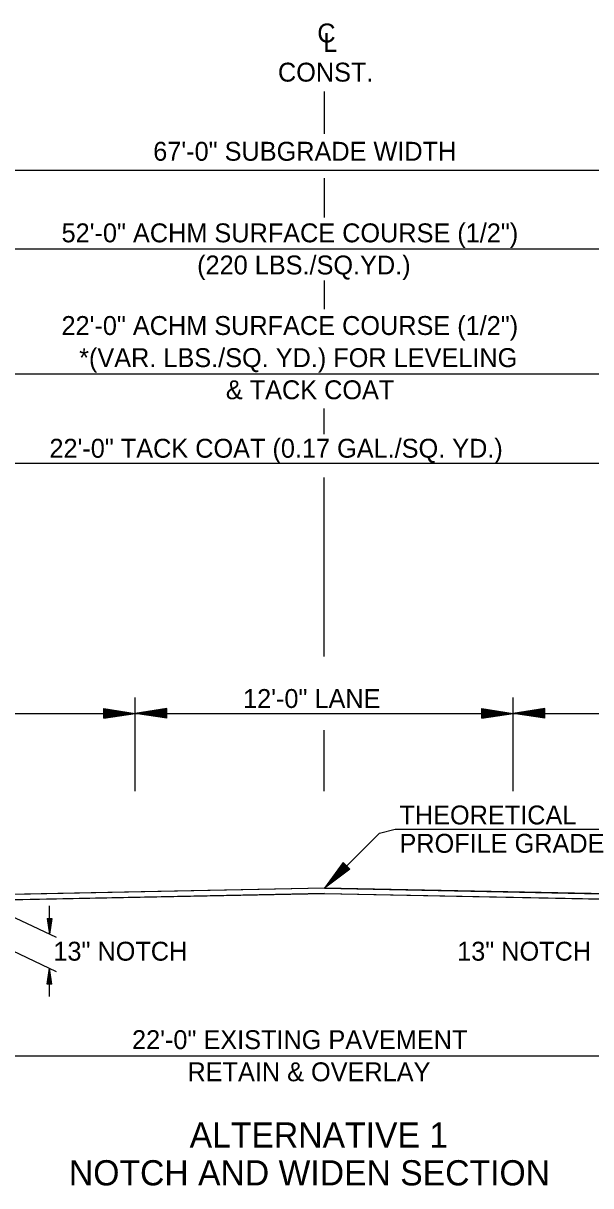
# Model space of a CAD drawing. Extents: x 1371763 to 1372860, y 385599 to 385872.
# Drawn here: x 1372073.83 to 1372091.85, y 385769.36 to 385806.27 of the extents above; entities that cross this region are included whole.
import ezdxf

# ---------------------------------------------------------------- set-up
doc = ezdxf.new("R2010")
doc.units = 0
doc.layers.add('R_Draft', color=7, linetype='Continuous')

msp = doc.modelspace()

# ---------------------------------------------------------------- linework, layer by layer
at = {"layer": 'R_Draft'}
for p, q in [((1372083.395, 385802.752), (1372083.395, 385804.102)), ((1372049.964, 385801.602), (1372116.827, 385801.602)), ((1372083.395, 385800.102), (1372083.395, 385801.352)), ((1372057.395, 385799.102), (1372109.395, 385799.102)), ((1372083.395, 385797.193), (1372083.395, 385798.102)), ((1372072.395, 385795.139), (1372094.395, 385795.14)), ((1372083.392, 385793.221), (1372083.392, 385794.031)), ((1372072.395, 385792.301), (1372094.395, 385792.301)), ((1372083.394, 385786.16), (1372083.392, 385791.841)), ((1372077.392, 385781.89), (1372077.393, 385784.864)), ((1372089.392, 385781.89), (1372089.393, 385784.864)), ((1372065.393, 385784.357), (1372077.393, 385784.357)), ((1372076.393, 385784.507), (1372077.393, 385784.357)), ((1372076.393, 385784.207), (1372076.393, 385784.507)), ((1372076.393, 385784.482), (1372077.226, 385784.357)), ((1372076.393, 385784.456), (1372077.054, 385784.357)), ((1372076.393, 385784.431), (1372076.887, 385784.357)), ((1372076.393, 385784.406), (1372076.718, 385784.357)), ((1372076.393, 385784.38), (1372076.551, 385784.357)), ((1372076.393, 385784.207), (1372077.393, 385784.357)), ((1372076.393, 385784.308), (1372076.718, 385784.357)), ((1372076.393, 385784.257), (1372077.054, 385784.357)), ((1372076.393, 385784.232), (1372077.226, 385784.357)), ((1372076.393, 385784.282), (1372076.887, 385784.357)), ((1372076.393, 385784.333), (1372076.551, 385784.357)), ((1372078.393, 385784.507), (1372077.393, 385784.357)), ((1372078.393, 385784.207), (1372077.393, 385784.357)), ((1372077.393, 385784.357), (1372089.393, 385784.357)), ((1372078.393, 385784.482), (1372077.56, 385784.357)), ((1372078.393, 385784.232), (1372077.56, 385784.357)), ((1372078.393, 385784.456), (1372077.732, 385784.357)), ((1372078.393, 385784.257), (1372077.732, 385784.357)), ((1372078.393, 385784.431), (1372077.898, 385784.357)), ((1372078.393, 385784.282), (1372077.898, 385784.357)), ((1372078.393, 385784.406), (1372078.068, 385784.357)), ((1372078.393, 385784.308), (1372078.068, 385784.357)), ((1372078.393, 385784.38), (1372078.235, 385784.357)), ((1372078.393, 385784.333), (1372078.235, 385784.357)), ((1372078.393, 385784.207), (1372078.393, 385784.507)), ((1372088.393, 385784.507), (1372089.393, 385784.357)), ((1372088.393, 385784.207), (1372088.393, 385784.507)), ((1372088.393, 385784.482), (1372089.226, 385784.357)), ((1372088.393, 385784.456), (1372089.054, 385784.357)), ((1372088.393, 385784.431), (1372088.887, 385784.357)), ((1372088.393, 385784.406), (1372088.718, 385784.357)), ((1372088.393, 385784.38), (1372088.551, 385784.357)), ((1372088.393, 385784.207), (1372089.393, 385784.357)), ((1372088.393, 385784.308), (1372088.718, 385784.357)), ((1372088.393, 385784.257), (1372089.054, 385784.357)), ((1372088.393, 385784.232), (1372089.226, 385784.357)), ((1372088.393, 385784.282), (1372088.887, 385784.357)), ((1372088.393, 385784.333), (1372088.551, 385784.357)), ((1372090.393, 385784.507), (1372089.393, 385784.357)), ((1372089.393, 385784.357), (1372101.393, 385784.357)), ((1372090.393, 385784.207), (1372089.393, 385784.357)), ((1372090.393, 385784.482), (1372089.56, 385784.357)), ((1372090.393, 385784.232), (1372089.56, 385784.357)), ((1372090.393, 385784.456), (1372089.732, 385784.357)), ((1372090.393, 385784.257), (1372089.732, 385784.357)), ((1372090.393, 385784.431), (1372089.898, 385784.357)), ((1372090.393, 385784.282), (1372089.898, 385784.357)), ((1372090.393, 385784.406), (1372090.068, 385784.357)), ((1372090.393, 385784.308), (1372090.068, 385784.357)), ((1372090.393, 385784.38), (1372090.235, 385784.357)), ((1372090.393, 385784.333), (1372090.235, 385784.357)), ((1372090.393, 385784.207), (1372090.393, 385784.507)), ((1372083.393, 385781.886), (1372083.392, 385783.827)), ((1372085.145, 385780.556), (1372085.645, 385780.681)), ((1372085.645, 385780.681), (1372092.822, 385780.681)), ((1372083.395, 385778.806), (1372085.145, 385780.556)), ((1372083.997, 385779.619), (1372083.395, 385778.806)), ((1372084.014, 385779.601), (1372083.514, 385778.924)), ((1372084.032, 385779.583), (1372083.635, 385779.045)), ((1372084.05, 385779.565), (1372083.753, 385779.163)), ((1372084.068, 385779.547), (1372083.873, 385779.283)), ((1372084.086, 385779.529), (1372083.991, 385779.401)), ((1372084.119, 385779.496), (1372083.991, 385779.401)), ((1372084.209, 385779.407), (1372083.997, 385779.619)), ((1372084.209, 385779.407), (1372083.395, 385778.806)), ((1372084.191, 385779.424), (1372083.514, 385778.924)), ((1372084.173, 385779.442), (1372083.635, 385779.045)), ((1372084.155, 385779.46), (1372083.753, 385779.163)), ((1372084.137, 385779.478), (1372083.873, 385779.283)), ((1372083.395, 385778.806), (1372065.395, 385778.446)), ((1372083.395, 385778.806), (1372101.395, 385778.446)), ((1372083.395, 385778.639), (1372065.305, 385778.277)), ((1372072.396, 385778.419), (1372074.884, 385777.247)), ((1372083.395, 385778.639), (1372101.486, 385778.277)), ((1372074.671, 385777.347), (1372074.671, 385778.247)), ((1372074.596, 385777.847), (1372074.671, 385777.347)), ((1372074.596, 385777.847), (1372074.746, 385777.847)), ((1372074.609, 385777.847), (1372074.671, 385777.431)), ((1372074.622, 385777.847), (1372074.671, 385777.517)), ((1372074.634, 385777.847), (1372074.671, 385777.6)), ((1372074.647, 385777.847), (1372074.671, 385777.685)), ((1372074.66, 385777.847), (1372074.671, 385777.768)), ((1372074.746, 385777.847), (1372074.671, 385777.347)), ((1372074.696, 385777.847), (1372074.671, 385777.685)), ((1372074.721, 385777.847), (1372074.671, 385777.517)), ((1372074.734, 385777.847), (1372074.671, 385777.431)), ((1372074.709, 385777.847), (1372074.671, 385777.6)), ((1372074.683, 385777.847), (1372074.671, 385777.768)), ((1372072.395, 385777.336), (1372074.883, 385776.164)), ((1372074.595, 385775.764), (1372074.67, 385776.264)), ((1372074.608, 385775.764), (1372074.67, 385776.18)), ((1372074.745, 385775.764), (1372074.67, 385776.264)), ((1372074.67, 385775.364), (1372074.67, 385776.264)), ((1372074.733, 385775.764), (1372074.67, 385776.18)), ((1372074.621, 385775.764), (1372074.67, 385776.094)), ((1372074.633, 385775.764), (1372074.67, 385776.011)), ((1372074.646, 385775.764), (1372074.67, 385775.926)), ((1372074.659, 385775.764), (1372074.67, 385775.843)), ((1372074.72, 385775.764), (1372074.67, 385776.094)), ((1372074.708, 385775.764), (1372074.67, 385776.011)), ((1372074.695, 385775.764), (1372074.67, 385775.926)), ((1372074.682, 385775.764), (1372074.67, 385775.843)), ((1372074.745, 385775.764), (1372074.595, 385775.764)), ((1372072.395, 385773.487), (1372094.395, 385773.487))]:
    msp.add_line(p, q, dxfattribs=at)
msp.add_lwpolyline([(1372083.395, 385778.806), (1372065.395, 385778.446), (1372057.395, 385778.126), (1372057.395, 385777.961), (1372065.305, 385778.277), (1372083.395, 385778.639), (1372094.395, 385778.419), (1372101.486, 385778.277), (1372109.395, 385777.961), (1372109.395, 385778.126), (1372101.395, 385778.446)], close=True, dxfattribs=at)

# ---------------------------------------------------------------- texts
for s, p in [('C', (1372083.171, 385805.658)), ('L', (1372083.357, 385805.358)), ('CONST.', (1372081.922, 385804.414)), ('67\'-0" SUBGRADE WIDTH', (1372077.962, 385801.902)), ('52\'-0" ACHM SURFACE COURSE (1/2")', (1372075.052, 385799.312)), ('(220 LBS./SQ.YD.)', (1372079.356, 385798.292)), ('22\'-0" ACHM SURFACE COURSE (1/2")', (1372075.049, 385796.37)), ('*(VAR. LBS./SQ. YD.) FOR LEVELING', (1372075.609, 385795.35)), ('& TACK COAT', (1372080.267, 385794.33)), ('22\'-0" TACK COAT (0.17 GAL./SQ. YD.)', (1372074.666, 385792.473)), ('12\'-0" LANE', (1372080.814, 385784.528)), ('22\'-0" EXISTING PAVEMENT', (1372077.289, 385773.697)), ('RETAIN & OVERLAY', (1372079.049, 385772.677))]:
    msp.add_text(s, height=0.6, rotation=360, dxfattribs=at).set_placement(p)
for s, height, p in [('THEORETICAL', 0.6, (1372085.779, 385780.831)), ('PROFILE GRADE', 0.6, (1372085.779, 385779.931)), ('13" NOTCH', 0.6, (1372074.791, 385776.506)), ('13" NOTCH', 0.6, (1372087.612, 385776.506)), ('ALTERNATIVE 1', 0.8, (1372079.118, 385770.571)), ('NOTCH AND WIDEN SECTION', 0.8, (1372075.285, 385769.371))]:
    msp.add_text(s, height=height, dxfattribs=at).set_placement(p)

doc.saveas('drawing.dxf')
